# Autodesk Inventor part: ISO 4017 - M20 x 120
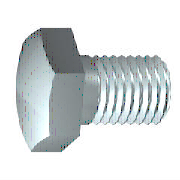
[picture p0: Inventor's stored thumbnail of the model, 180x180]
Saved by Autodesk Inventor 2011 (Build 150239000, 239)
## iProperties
Created: 2010-02
Part Number: ISO 4017 - M20 x 120
Material: Stainless Steel, 440C
Description: Hexagon head screws
Document SubType Name: Modeling
Standard: ISO 4017
Designer: 129877
Standard Revision: Third edition 1999-08-15
Standards Organization: ISO
Language: en-US
Size Designation: M20 x 120
Categories: <MemberInstance><Categories><Category DisplayName="Fasteners" InternalName="e4da775c-781d-43d5-af7c-5136215cf5a6" Mnemonic="FSTN"><Category DisplayName="Bolts"
Density: 7.75 g/cm^3
Mass: 365.942 g
Surface Area: 102.894 cm^2
Volume: 47.2183 cm^3
IsCustomPart: 0
Author: 129877
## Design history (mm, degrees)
body "Solid1"
workplane "Work Plane1"
revolve "Body" stored, may be unused: angle "d12" = 90 deg
sketch "Sketch2"
  geometry: L1 (0, 17.321)-(15, 8.66); L2 (15, 8.66)-(15, -8.66); L3 (15, -8.66)-(0, -17.321); L4 (0, -17.321)-(-15, -8.66); L5 (-15, -8.66)-(-15, 8.66); L6 (-15, 8.66)-(0, 17.321); 2 further points
  constraints: 12 end point, 1 coincident, 1 vertical, 11 other
  dimensions: "d11" = 30 distance between parallel lines of L5 L2 (= SW)
extrude "Head" join sketch "Sketch2" distance "d3" = 11.7 (= KOH - SD); taper "d4" = 0 deg
revolve "Chamfer1" stored, may be unused: angle "d21" = 90 deg
feature "Thread" dims "d15" = 112.5 (= GEL), "d16" = 0
chamfer "Chamfer2" distance "d6" = 1.53363 (= -0.5 x SPD + 0.5 x GD); stored, may be unused: second distance "d7" = 1.53373 (computed from GUL), angle "d55" = 45 deg
sketch "Sketch1"
  geometry: L1 (0, 14.095)-(0, 10); L2 (7.5, 10)-(120, 10); L3 (120, 10)-(120, 0); L4 (120, 0)-(-0.8, 0); L5 (-24.96, 0)-(144.16, 0) reference; L6 (-0.8, 0)-(-0.8, 14.095); L7 (-0.8, 14.095)-(0, 14.095); L8 (7.5, 10)-(5.966, 10); L9 (5.966, 10)-(0, 10); L10 (0, -2.819)-(0, 16.914) reference
  constraints: 16 end point, 2 collinear, 2 perpendicular, 1 parallel
  dimensions: "d0" = 120 distance between parallel lines of L3 L1 (= NLG); "d1" = 112.5 distance from line of L2.start L3 (= GEL); "d2" = 20 diameter of L2 L4 (= GD); "d9" = 0.8001 distance between parallel lines of L6 L1 (computed from SD); "d10" = 28.19 diameter of L7 L4 (= SD2); "d13" = 1.53373 distance of L2.start L8.end (computed from GAL); "d14" = 20 diameter of L9 L4 (= BDM)
sketch "Sketch4"
  geometry: L1 (-12.5, 15)-(-12.5, 17.321); L2 (-12.5, 17.321)-(-11.16, 17.321); L3 (-11.16, 17.321)-(-12.5, 15); L4 (-14.84, 0)-(1.54, 0) reference; L5 (-0.8, 17.321)-(-12.5, 17.321) reference; L6 (-12.5, 8.66)-(-12.5, 17.321) reference
  constraints: 6 end point, 2 collinear, 1 perpendicular, 1 vertical
  dimensions: "d5" = 30 deg angle of L3 L1 (= ANG1); "d19" = 30 diameter of L1.start L4 (= SW0)
other parameters: "NLG" = 120 [user parameter; used in 1 equation term], "GD" = 20 (= NND) [user parameter; used in 2 equation terms], "BDM" = 20 (= NND) [user parameter; used in 1 equation term], "KOH" = 12.5 [user parameter; used in 1 equation term], "GEL" = 112.5 [user parameter; used in 2 equation terms], "SW" = 30 [user parameter; used in 2 equation terms], "SW0" = 30 (= SW) [user parameter; used in 1 equation term], "SPD" = 16.93275 (= NND - 1.2269 x PTC) [user parameter; used in 1 equation term], "SD2" = 28.19 [user parameter; used in 2 equation terms], "SD" = 0.8 [user parameter; used in 2 equation terms], "ANG1" = 30 deg [user parameter; used in 1 equation term], "GAL" = 1.53363 (= 0.61345 x PTC) [user parameter; used in 1 equation term], "GUL" = 1.53363 (= 0.61345 x PTC) [user parameter; used in 1 equation term], "d8" = 0, "RR" = 0.8 [user parameter], "d57" = 0, "d58" = 0, "TPU" = 4 (computed from PTC) [user parameter], "GD1" = 16.93275 (= THREADDIA - 1.2269 x PTC) [user parameter], "SDH" = 28.19 (= SD2) [user parameter], "SDHG" = 7.5 [user parameter], "TOA" = 30 deg [user parameter], "PTC" = 2.5 [user parameter; used in 5 equation terms], "E0" = 34.65 [user parameter]
